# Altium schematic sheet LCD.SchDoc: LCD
size A4; CompanyName: STMicroelectronics; Organization: Microcontrollers Division; DocumentNumber: 16; SheetNumber: 12; SheetTotal: 19
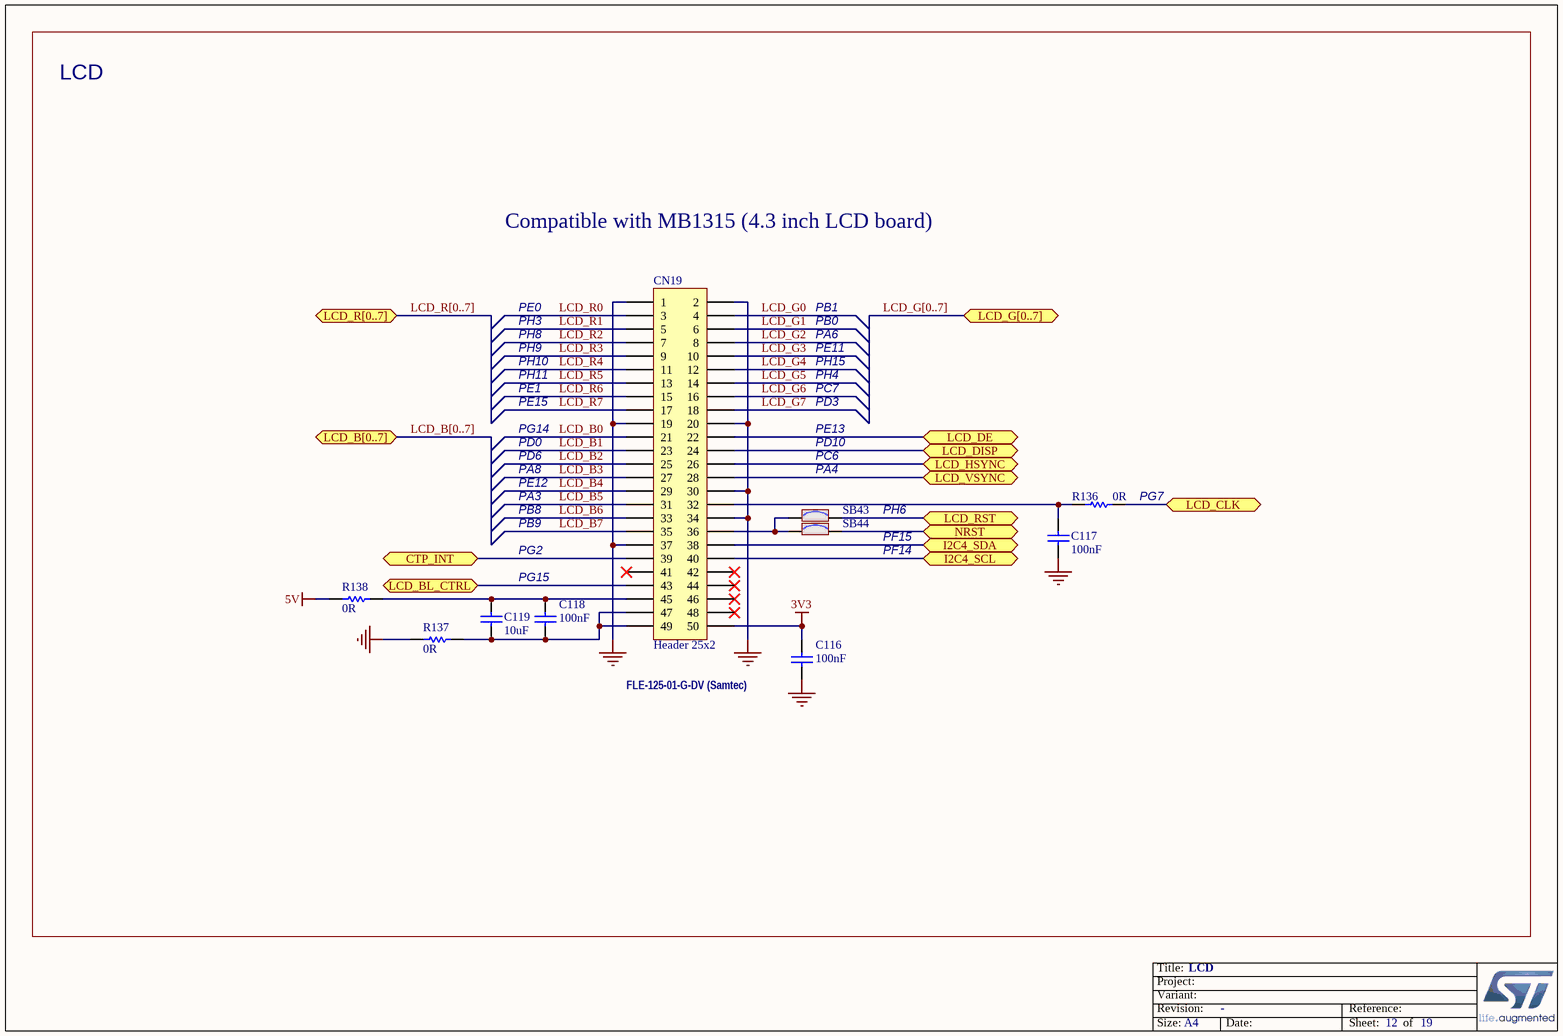
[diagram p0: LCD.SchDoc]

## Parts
C116  value 100nF  [C0402]  (hidden comment: Capacitor)
C117  value 100nF  [C0402]  (hidden comment: Capacitor)
C118  value 100nF  [C0402]  (hidden comment: Capacitor)
C119  value 10uF  [C0805]  (hidden comment: Capacitor)
CN19  Header 25x2  [MOD_LCD_MB1046B__CON_SAMTEC_FLE-125-01-G-DV]
R136  value 0R  [R0402]  (hidden comment: Resistor)
R137  value 0R  [R0603]  (hidden comment: Resistor)
R138  value 0R  [R0603]  (hidden comment: Resistor)
SB43  SB_ON  [SOLDER-BRIDGE_R0603-0R]  (value not drawn)
SB44  SB_ON  [SOLDER-BRIDGE_R0603-0R]  (value not drawn)

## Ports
CTP_INT, I2C4_SCL, I2C4_SDA, LCD_B[0..7], LCD_BL_CTRL, LCD_CLK, LCD_DE, LCD_DISP, LCD_G[0..7], LCD_HSYNC, LCD_R[0..7], LCD_RST, LCD_VSYNC, NRST

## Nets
3V3: C116.1 CN19.50
5V: R138.1
GND: C116.2 C117.1 CN19.1 CN19.2 CN19.19 CN19.20 CN19.30 CN19.34 CN19.37 R137.1
CTP_INT: CN19.39 ; port CTP_INT
I2C4_SCL: CN19.40 ; port I2C4_SCL
I2C4_SDA: CN19.38 ; port I2C4_SDA
LCD_B0: CN19.21
LCD_B1: CN19.23
LCD_B2: CN19.25
LCD_B3: CN19.27
LCD_B4: CN19.29
LCD_B5: CN19.31
LCD_B6: CN19.33
LCD_B7: CN19.35
LCD_BL_CTRL: CN19.43 ; port LCD_BL_CTRL
LCD_CLK: R136.2 ; port LCD_CLK
LCD_DE: CN19.22 ; port LCD_DE
LCD_DISP: CN19.24 ; port LCD_DISP
LCD_G0: CN19.4
LCD_G1: CN19.6
LCD_G2: CN19.8
LCD_G3: CN19.10
LCD_G4: CN19.12
LCD_G5: CN19.14
LCD_G6: CN19.16
LCD_G7: CN19.18
LCD_HSYNC: CN19.26 ; port LCD_HSYNC
LCD_R0: CN19.3
LCD_R1: CN19.5
LCD_R2: CN19.7
LCD_R3: CN19.9
LCD_R4: CN19.11
LCD_R5: CN19.13
LCD_R6: CN19.15
LCD_R7: CN19.17
LCD_RST: SB43.2 ; port LCD_RST
LCD_VSYNC: CN19.28 ; port LCD_VSYNC
NRST: SB44.2 ; port NRST
NetC117_2: C117.2 CN19.32 R136.1
NetC118_1: C118.1 C119.2 CN19.45 R138.2
NetC118_2: C118.2 C119.1 CN19.47 CN19.49 R137.2
NetCN19_36: CN19.36 SB43.1 SB44.1

Not connected (* = marked no-connect by the designer): CN19 41* 42* 44* 46* 48*

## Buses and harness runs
bus LCD_B[0..7] = port LCD_B[0..7]
bus LCD_G[0..7] = port LCD_G[0..7]
bus LCD_R[0..7] = port LCD_R[0..7]

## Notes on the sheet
- LCD
- Compatible with MB1315 (4.3 inch LCD board)
- PE0
- PB1
- PH3
- PH8
- PH9
- PH10
- PH11
- PA6
- PB0
- PE11
- PH15
- PH4
- PE1
- PD0
- PE15
- PG14
- PE13
- PD10
- PC7
- PD3
- PA3
- PA8
- PB8
- PD6
- PE12
- PA4
- PC6
- PH6
- (near R136) PG7
- PG2
- PG15
- PB9
- PF15
- PF14
- (near C116) FLE-125-01-G-DV (Samtec)

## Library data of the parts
C116-C118 = MCD-00006: Capacitor, MLCC, 100nF, 16V, X7R, 10%, 0402, T=0.5mm; Manufacturer_Part_Number: CC0402KRX7R7BB104; Manufacturer: YAGEO; Provided_By: Subcon; Initial_Board_Reference: MB1274
C119 = MCD-00014: Capacitor, MLCC, 10uF, 25V, X5R, 10%, 0805, T=0,85mm; Manufacturer_Part_Number: CC0805KRX5R8BB106; Manufacturer: YAGEO; Provided_By: Subcon; Initial_Board_Reference: MB1274
CN19 = MCD-01222: Header 25x2 for MB1046 - LCD 4.3 inches daughter board; Part_Type: Connector; Manufacturer_Part_Number: FLE-125-01-G-DV; Manufacturer: SAMTEC; Provided_By: SUBCO; Initial_Board_Reference: MB1332
R136 = MCD-00052: Resistor,0R,0402,5%,1/16W; Manufacturer_Part_Number: RC0402JR-070RL; Manufacturer: YAGEO; ECCN_US: EAR99; ECCN_EU: NEC; Provided_By: SUBCO
R137 R138 = MCD-00056: Resistor,0R,0603,5%,1/10W; Manufacturer_Part_Number: RC0603JR-070RL; Manufacturer: YAGEO; Provided_By: subcon; Initial_Board_Reference: MB1274
SB43 SB44 = MCD-00071: Solder Bridge ON; Part_Type: Mechanical; Manufacturer_Part_Number: RC0603JR-070RL; Manufacturer: YAGEO; Provided_By: SUBCO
